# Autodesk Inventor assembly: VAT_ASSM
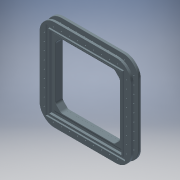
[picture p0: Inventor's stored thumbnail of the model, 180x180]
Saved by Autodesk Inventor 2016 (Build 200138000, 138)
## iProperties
Created: 2016-01
Part Number: VAT_ASSM
Document SubType Name: Assembly
Designer: John
Sending System: SIEMENS PLM Software NX 7.5
Preprocessor: ST-DEVELOPER v11
Title: VAT_ASSM.stp
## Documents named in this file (5)
- D:\3D Printer Designs\John Ledden Designs\DLP Printer\Vat-v3\VAT_ASSM.iam
- D:\3D Printer Designs\John Ledden Designs\DLP Printer\Vat-v3\Top_Clamp.ipt
- D:\3D Printer Designs\John Ledden Designs\DLP Printer\Vat-v3\FEP_FILM.ipt
- D:\3D Printer Designs\John Ledden Designs\DLP Printer\Vat-v3\3D_Riser.ipt
- D:\3D Printer Designs\John Ledden Designs\DLP Printer\Vat-v3\Base.ipt
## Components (4 placed, 4 different names)
1. Top_Clamp_1002
2. FEP_FILM_1003
3. 3D_Riser_1004
4. Base_1005
